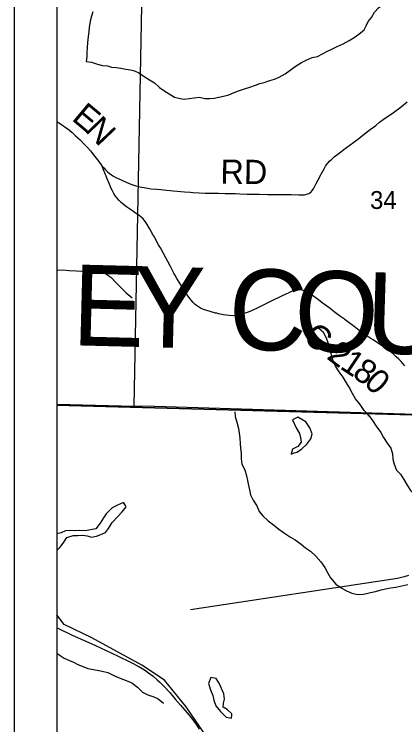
# Model space of a CAD drawing. Extents: x 0 to 34, y 0 to 22.
# Drawn here: x 2 to 2.916, y 14.912 to 16.577 of the extents above; entities that cross this region are included whole.
import ezdxf

# ---------------------------------------------------------------- set-up
doc = ezdxf.new("R2010")
doc.units = 0
for name, color, linetype in [('GM_X_Corporation', 7, 'Continuous'), ('GM_X_County_Road', 7, 'Continuous'), ('GM_X_County_Road_Text', 7, 'Continuous'), ('GM_X_County_Text', 7, 'Continuous'), ('GM_X_Minor_Lake', 7, 'Continuous'), ('GM_X_Minor_River', 7, 'Continuous'), ('GM_X_Rail_Line', 7, 'Continuous'), ('GM_X_Section_Text', 7, 'Continuous'), ('GM_X_State_Route', 7, 'Continuous'), ('GM_X_Township_Road', 7, 'Continuous'), ('SH_Data', 7, 'Continuous')]:
    doc.layers.add(name, color=color, linetype=linetype)

msp = doc.modelspace()

# ---------------------------------------------------------------- linework, layer by layer
at = {"layer": 'GM_X_Corporation'}
for points in [[(2.1, 20.9), (2.1, 15.6606), (2.9609, 15.6375), (2.9828, 15.6366), (4.3545, 15.5959)], [(2.1, 20.9), (2.1, 15.6606), (2.9609, 15.6375), (2.9828, 15.6366), (4.3545, 15.5959)], [(4.3545, 15.5959), (2.9828, 15.6366), (2.9609, 15.6375), (2.1, 15.6606), (2.1, 14.1), (8.9, 14.1)]]:
    msp.add_lwpolyline(points, dxfattribs=at)
for points in [[(2.1, 16.6849), (2.1, 15.6631), (2.2815, 15.6586), (2.3008, 16.6793)], [(2.3008, 16.6793), (3.3284, 16.656), (3.2981, 15.6275), (2.3289, 15.6573), (2.2815, 15.6586)], [(2.1, 15.6606), (2.1, 14.1), (4.3124, 14.1), (4.324, 14.5949), (4.3241, 14.5964), (4.3352, 14.9629), (4.3354, 14.967), (4.3388, 15.081), (4.3545, 15.5959), (2.9828, 15.6366), (2.9609, 15.6375)]]:
    msp.add_lwpolyline(points, close=True, dxfattribs=at)
at = {"layer": 'GM_X_County_Road'}
for points in [[(2.2063, 16.2208), (2.21, 16.2164), (2.2142, 16.2119), (2.2187, 16.2076), (2.223, 16.204), (2.2279, 16.2004), (2.2326, 16.1973), (2.2386, 16.194), (2.2436, 16.1915), (2.2526, 16.1874), (2.2612, 16.1836), (2.2692, 16.1803), (2.2779, 16.1769), (2.2855, 16.1744), (2.2921, 16.1727), (2.2988, 16.1712), (2.3043, 16.1702), (2.308, 16.1696), (2.3129, 16.1688), (2.3203, 16.1678), (2.3345, 16.1664), (2.3437, 16.1657), (2.3499, 16.1652), (2.3579, 16.1644), (2.3654, 16.1637), (2.3728, 16.163), (2.382, 16.1621), (2.3993, 16.1605), (2.4135, 16.1594), (2.4184, 16.1591), (2.4338, 16.1582), (2.448, 16.1576), (2.4641, 16.1574), (2.479, 16.1571), (2.4944, 16.1568), (2.5037, 16.1566), (2.5118, 16.1563), (2.5186, 16.1561), (2.5292, 16.1558), (2.5459, 16.1553), (2.5614, 16.1551), (2.567, 16.1551), (2.5744, 16.1549), (2.5941, 16.1545), (2.5996, 16.1544), (2.6058, 16.1543), (2.6168, 16.1543), (2.6267, 16.1544), (2.6359, 16.1543), (2.6433, 16.154), (2.6458, 16.154), (2.6495, 16.1539), (2.6674, 16.1531), (2.6754, 16.1531), (2.6803, 16.1535), (2.6834, 16.1541), (2.6875, 16.1554), (2.6903, 16.1567), (2.6929, 16.1583), (2.6967, 16.1615), (2.6987, 16.1638), (2.7013, 16.1673), (2.705, 16.1738), (2.7082, 16.1799), (2.7127, 16.1887), (2.7204, 16.2036), (2.7265, 16.2145), (2.73, 16.2203), (2.7343, 16.2264), (2.7391, 16.2321), (2.7445, 16.2372), (2.7501, 16.2421), (2.7585, 16.2486), (2.7728, 16.2595), (2.7792, 16.2644), (2.7962, 16.2769), (2.8076, 16.2855), (2.8126, 16.2892), (2.8215, 16.2959), (2.8347, 16.3062), (2.8474, 16.3162), (2.8567, 16.3233), (2.8653, 16.3295), (2.88, 16.3397), (2.8861, 16.3441), (2.8921, 16.3485), (2.9039, 16.3575), (2.9123, 16.364), (2.921, 16.371)], [(2.1, 16.3253), (2.1049, 16.3224), (2.1132, 16.3169), (2.1217, 16.3107), (2.1294, 16.3045), (2.1356, 16.2993), (2.1439, 16.2919), (2.1543, 16.2821), (2.1643, 16.272), (2.172, 16.2639), (2.1785, 16.2565), (2.1809, 16.2536), (2.189, 16.2434), (2.1925, 16.239), (2.1981, 16.2316), (2.2056, 16.2217), (2.2063, 16.2208)], [(2.9161, 15.7525), (2.9121, 15.7572), (2.9071, 15.7628), (2.9016, 15.7686), (2.8957, 15.7741), (2.8881, 15.7805), (2.8803, 15.7867), (2.8729, 15.7923), (2.8627, 15.7995), (2.8519, 15.8065), (2.8411, 15.8136), (2.8364, 15.8165), (2.8311, 15.8198), (2.8237, 15.8244), (2.8162, 15.8299), (2.8103, 15.8344), (2.8088, 15.8355), (2.797, 15.8446), (2.7822, 15.856), (2.7762, 15.8604), (2.7742, 15.8619), (2.7651, 15.8683), (2.7625, 15.8701), (2.7497, 15.8796), (2.7458, 15.8826), (2.7403, 15.8867), (2.7329, 15.8924), (2.722, 15.9006), (2.713, 15.9073), (2.7025, 15.9149), (2.6943, 15.9206), (2.6863, 15.9254), (2.6825, 15.9273), (2.6773, 15.9294), (2.675, 15.93), (2.6689, 15.931), (2.6653, 15.9309), (2.6615, 15.9305), (2.6555, 15.9289), (2.6515, 15.9273), (2.6435, 15.9238), (2.6351, 15.9197), (2.63, 15.9173), (2.6267, 15.9157), (2.6021, 15.9039), (2.5865, 15.8962), (2.5709, 15.8885), (2.5579, 15.8826), (2.5487, 15.8787), (2.5417, 15.8762), (2.5346, 15.874), (2.5274, 15.8722), (2.52, 15.8709), (2.512, 15.8702), (2.5039, 15.8704), (2.4977, 15.8711), (2.4904, 15.8723), (2.4789, 15.8749), (2.4747, 15.876), (2.4722, 15.8765), (2.459, 15.8799), (2.4512, 15.8822), (2.4436, 15.8849), (2.4368, 15.8878), (2.4319, 15.8906), (2.4274, 15.8938), (2.4241, 15.8966), (2.4193, 15.9014), (2.4148, 15.9066), (2.4103, 15.9125), (2.4049, 15.9201), (2.3983, 15.9299), (2.393, 15.9383), (2.3866, 15.949), (2.3816, 15.9575), (2.3769, 15.9656), (2.3745, 15.9699), (2.3654, 15.9869), (2.3598, 15.9973), (2.3551, 16.006), (2.3426, 16.029), (2.3384, 16.0366), (2.3293, 16.0528), (2.3263, 16.0582), (2.3245, 16.0615), (2.3232, 16.0636), (2.3172, 16.0745), (2.3116, 16.0841), (2.3104, 16.0863), (2.3077, 16.0904), (2.305, 16.0939), (2.3021, 16.0971), (2.298, 16.1008), (2.2921, 16.1054), (2.2845, 16.1108), (2.2804, 16.1135), (2.2701, 16.1203), (2.263, 16.1253), (2.2562, 16.1306), (2.2507, 16.1356), (2.2458, 16.1404), (2.2404, 16.1463), (2.2359, 16.1522), (2.2333, 16.1564), (2.2301, 16.1624), (2.2272, 16.1685), (2.2231, 16.1782), (2.2181, 16.1909), (2.2124, 16.2047), (2.2105, 16.2099), (2.2063, 16.2208)]]:
    msp.add_lwpolyline(points, dxfattribs=at)
at = {"layer": 'GM_X_Minor_Lake'}
for points in [[(2.6526, 15.6263), (2.661, 15.6071), (2.669, 15.5939), (2.6714, 15.584), (2.6726, 15.5742), (2.6647, 15.5635), (2.6527, 15.5578), (2.649, 15.546), (2.6563, 15.5485)], [(2.6563, 15.5485), (2.6625, 15.5506), (2.6738, 15.5572), (2.6859, 15.5694), (2.6952, 15.5816), (2.6985, 15.5937), (2.6932, 15.6073), (2.6836, 15.6216), (2.6741, 15.6273), (2.6646, 15.6321), (2.6526, 15.6263)], [(2.2608, 15.4252), (2.2564, 15.4322), (2.2425, 15.426), (2.2297, 15.4203), (2.2158, 15.4058), (2.2094, 15.3963), (2.2016, 15.3837), (2.1911, 15.3711), (2.1786, 15.3684), (2.1661, 15.3664), (2.1533, 15.3667), (2.1423, 15.3662), (2.1321, 15.3669), (2.12, 15.3665), (2.1102, 15.3618), (2.1, 15.359)], [(2.1, 15.3198), (2.1066, 15.327), (2.1149, 15.3369), (2.1235, 15.3502), (2.1386, 15.3552), (2.1484, 15.3553), (2.1598, 15.3561), (2.1707, 15.3543), (2.181, 15.3514), (2.1931, 15.3533), (2.2029, 15.3572), (2.2142, 15.3622), (2.2209, 15.3717), (2.2299, 15.3854), (2.2423, 15.3988), (2.2532, 15.411), (2.2626, 15.4224), (2.2608, 15.4252)], [(2.5099, 14.9341), (2.5102, 14.9376), (2.4996, 14.9478), (2.4897, 14.9526), (2.4908, 14.9625), (2.4933, 14.972), (2.4917, 14.9845), (2.4856, 14.9969), (2.4814, 15.0075), (2.4733, 15.02), (2.4608, 15.0221), (2.4553, 15.0088)], [(2.4553, 15.0088), (2.4603, 14.9937), (2.4657, 14.9805), (2.468, 14.9695), (2.4723, 14.9559), (2.4837, 14.9431), (2.4967, 14.9299), (2.5092, 14.9274), (2.5099, 14.9341)]]:
    msp.add_lwpolyline(points, dxfattribs=at)
at = {"layer": 'GM_X_Minor_River'}
for points in [[(2.7713, 16.5074), (2.7853, 16.5148), (2.7973, 16.5221), (2.8082, 16.5298), (2.8202, 16.5401), (2.825, 16.5497), (2.8295, 16.5592), (2.8377, 16.5691), (2.8444, 16.5813), (2.8541, 16.5917), (2.8665, 16.6009), (2.8781, 16.6151), (2.8859, 16.6258), (2.8911, 16.6387), (2.8955, 16.6505), (2.8996, 16.66), (2.904, 16.6729), (2.9107, 16.6863)], [(2.1847, 16.5824), (2.181, 16.5721), (2.1777, 16.5603), (2.1756, 16.5455), (2.1746, 16.5353), (2.1732, 16.5243), (2.1722, 16.5106), (2.1708, 16.4977), (2.1705, 16.4871), (2.1702, 16.4776), (2.1688, 16.4655), (2.1814, 16.4641), (2.1931, 16.4604), (2.2064, 16.456), (2.2185, 16.4554), (2.2284, 16.4528), (2.2394, 16.4518), (2.2496, 16.4504), (2.2614, 16.4479), (2.2724, 16.4461), (2.2822, 16.4439), (2.2921, 16.4391), (2.3024, 16.4324), (2.3169, 16.4227), (2.3291, 16.4156), (2.3405, 16.4047), (2.3508, 16.398), (2.3634, 16.3902), (2.3756, 16.3823), (2.3889, 16.3787), (2.3987, 16.3777), (2.4105, 16.3793), (2.4222, 16.3806), (2.4343, 16.3822), (2.4472, 16.3793), (2.4581, 16.3787), (2.4687, 16.3799), (2.4797, 16.3823), (2.4906, 16.3843), (2.5031, 16.3875), (2.5155, 16.3929), (2.5261, 16.3968), (2.5397, 16.4015), (2.5521, 16.4054), (2.5657, 16.4105), (2.5759, 16.4144), (2.5861, 16.4168), (2.5996, 16.4211), (2.6098, 16.4246), (2.6215, 16.4289), (2.6354, 16.4366), (2.6467, 16.4451), (2.6606, 16.4558), (2.6738, 16.4636), (2.6847, 16.4686), (2.6986, 16.4748), (2.7111, 16.4776), (2.7224, 16.4834), (2.7348, 16.4896), (2.7465, 16.4954), (2.757, 16.5008), (2.7713, 16.5074)], [(2.1, 15.9763), (2.1024, 15.9765), (2.1141, 15.9774), (2.1292, 15.9757), (2.1459, 15.9751), (2.1584, 15.9748), (2.1693, 15.9768), (2.1826, 15.977), (2.1928, 15.9756), (2.2057, 15.973), (2.2168, 15.9667), (2.2263, 15.9604), (2.2389, 15.9472), (2.2504, 15.9352), (2.2622, 15.924), (2.2764, 15.912)], [(2.8288, 15.6362), (2.8315, 15.6361), (2.8207, 15.6482), (2.8107, 15.6625), (2.8, 15.6753), (2.793, 15.6881), (2.7849, 15.7024), (2.7788, 15.7126), (2.7715, 15.7261), (2.7619, 15.7389), (2.753, 15.7517), (2.7476, 15.7646), (2.7437, 15.7774), (2.7405, 15.791), (2.737, 15.8039), (2.7319, 15.8178), (2.7253, 15.831), (2.7143, 15.84)], [(2.5169, 15.6448), (2.5178, 15.6339), (2.5217, 15.6207), (2.5256, 15.6056), (2.5275, 15.5946), (2.5288, 15.584), (2.5296, 15.5696), (2.5305, 15.5597), (2.5317, 15.5484), (2.5318, 15.5351), (2.5338, 15.5226), (2.5407, 15.509), (2.5442, 15.495), (2.5466, 15.4844), (2.5493, 15.4723), (2.5513, 15.4625), (2.554, 15.4504), (2.5598, 15.4376), (2.569, 15.4244), (2.5744, 15.4115), (2.5828, 15.4014), (2.595, 15.3897), (2.6079, 15.3803), (2.6201, 15.3698), (2.6334, 15.3605), (2.6479, 15.3515), (2.6589, 15.3447), (2.6726, 15.335), (2.6825, 15.3264), (2.6943, 15.3181), (2.7073, 15.3069), (2.7191, 15.2933), (2.7279, 15.2805), (2.7356, 15.2669), (2.7417, 15.256), (2.7543, 15.2409), (2.7665, 15.2323), (2.7787, 15.2259), (2.7916, 15.2204), (2.8014, 15.2178), (2.8143, 15.2171), (2.8256, 15.2195), (2.8355, 15.2215), (2.8468, 15.2242), (2.8604, 15.2281), (2.8706, 15.2305), (2.8819, 15.2329), (2.8948, 15.2341), (2.9084, 15.2372), (2.9224, 15.2404)], [(2.8315, 15.6361), (2.8402, 15.6248), (2.8483, 15.6116), (2.8594, 15.5965), (2.8655, 15.5848), (2.8743, 15.5713), (2.8831, 15.56), (2.8866, 15.5467), (2.8875, 15.5339), (2.8906, 15.5225), (2.896, 15.5085), (2.9052, 15.4988), (2.9132, 15.4863), (2.9209, 15.4731), (2.9293, 15.461), (2.9389, 15.4494), (2.9488, 15.4373), (2.9576, 15.4245), (2.9611, 15.4105), (2.9639, 15.398), (2.9663, 15.384), (2.969, 15.3719), (2.9725, 15.3598), (2.9782, 15.3476)], [(2.1, 15.0792), (2.1051, 15.0756), (2.1173, 15.0681), (2.1299, 15.0622), (2.1393, 15.0585), (2.1492, 15.0532), (2.1595, 15.0488), (2.1724, 15.0436), (2.1944, 15.04), (2.2065, 15.037), (2.2198, 15.0341), (2.2353, 15.0266), (2.2463, 15.0218), (2.2566, 15.0181), (2.2661, 15.014), (2.2756, 15.0103), (2.2889, 15.0002), (2.3007, 14.9878), (2.3136, 14.9818), (2.3273, 14.977), (2.3375, 14.9725), (2.3497, 14.9624)]]:
    msp.add_lwpolyline(points, dxfattribs=at)
at = {"layer": 'GM_X_Rail_Line'}
msp.add_lwpolyline([(2.5176, 14.1), (2.3379, 14.4045), (2.3157, 14.5571), (2.3458, 14.6427), (2.3702, 14.6821), (2.4522, 14.7687), (2.4717, 14.8009), (2.4568, 14.8751), (2.4034, 14.9541), (2.3521, 15.0161), (2.2989, 15.051), (2.1818, 15.1154), (2.1168, 15.1468), (2.1, 15.1695)], dxfattribs=at)
at = {"layer": 'GM_X_State_Route'}
msp.add_lwpolyline([(2.1, 15.1391), (2.1022, 15.138), (2.1361, 15.122), (2.1889, 15.0979), (2.2418, 15.0732), (2.274, 15.0577), (2.2907, 15.049), (2.3052, 15.0401), (2.315, 15.0334), (2.3256, 15.0254), (2.3354, 15.0171), (2.3416, 15.0113), (2.352, 15.0009), (2.3645, 14.9872), (2.3782, 14.971), (2.3898, 14.9574), (2.4052, 14.9395), (2.416, 14.927), (2.4258, 14.9139), (2.4334, 14.9011)], dxfattribs=at)
at = {"layer": 'GM_X_Township_Road'}
msp.add_lwpolyline([(2.9241, 15.2617), (2.9141, 15.2586), (2.8982, 15.2544), (2.4136, 15.1813)], dxfattribs=at)
at = {"layer": 'SH_Data'}
for p, q in [((2, 21), (2, 14)), ((2.1, 20.9), (2.1, 14.1))]:
    msp.add_line(p, q, dxfattribs=at)

# ---------------------------------------------------------------- texts
at = {"layer": 'GM_X_County_Road_Text'}
for s, height, rotation, p in [('E', 0.0568, 320.0156, (2.1326, 16.3299)), ('N', 0.0568, 313.7468, (2.164, 16.3037)), ('RD', 0.05682, 359.5107, (2.4833, 16.1793)), ('C', 0.0568, 322.3167, (2.6741, 15.8143)), ('-', 0.0568, 322.4228, (2.7111, 15.7857)), ('2', 0.0568, 322.977, (2.7301, 15.7711)), ('1', 0.0568, 326.4146, (2.7611, 15.7479)), ('8', 0.0568, 325.135, (2.7899, 15.7287)), ('0', 0.0568, 317.3189, (2.8171, 15.71))]:
    msp.add_text(s, height=height, rotation=rotation, dxfattribs=at).set_placement(p)
at = {"layer": 'GM_X_County_Text'}
for s, rotation, p in [('E', 358.5322, (2.1343, 15.801)), ('Y', 358.5329, (2.2759, 15.7974)), ('C', 358.5322, (2.5009, 15.7916)), ('O', 358.5253, (2.655, 15.7876)), ('U', 358.2572, (2.8222, 15.7833))]:
    msp.add_text(s, height=0.1894, rotation=rotation, dxfattribs=at).set_placement(p)
at = {"layer": 'GM_X_Section_Text'}
msp.add_text('34', height=0.04186, rotation=0, dxfattribs=at).set_placement((2.8342, 16.1203))

doc.saveas('drawing.dxf')
